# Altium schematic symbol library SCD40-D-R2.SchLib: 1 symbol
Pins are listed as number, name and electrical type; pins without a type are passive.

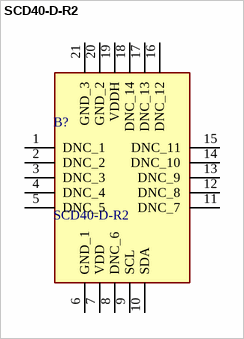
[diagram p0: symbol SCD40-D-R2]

## SCD40-D-R2
designator B?
Air Quality Sensor CO2 Sensor 2.5V/3.3V/5V 20-Pin SMD EP; Manufacturer_Name: Sensirion; Geometry.Height: 6.8mm
footprint SCD40DR2
pins: 1 DNC_1, 2 DNC_2, 3 DNC_3, 4 DNC_4, 5 DNC_5, 6 GND_1, 7 VDD, 8 DNC_6, 9 SCL, 10 SDA, 11 DNC_7, 12 DNC_8, 13 DNC_9, 14 DNC_10, 15 DNC_11, 16 DNC_12, 17 DNC_13, 18 DNC_14, 19 VDDH, 20 GND_2, 21 GND_3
